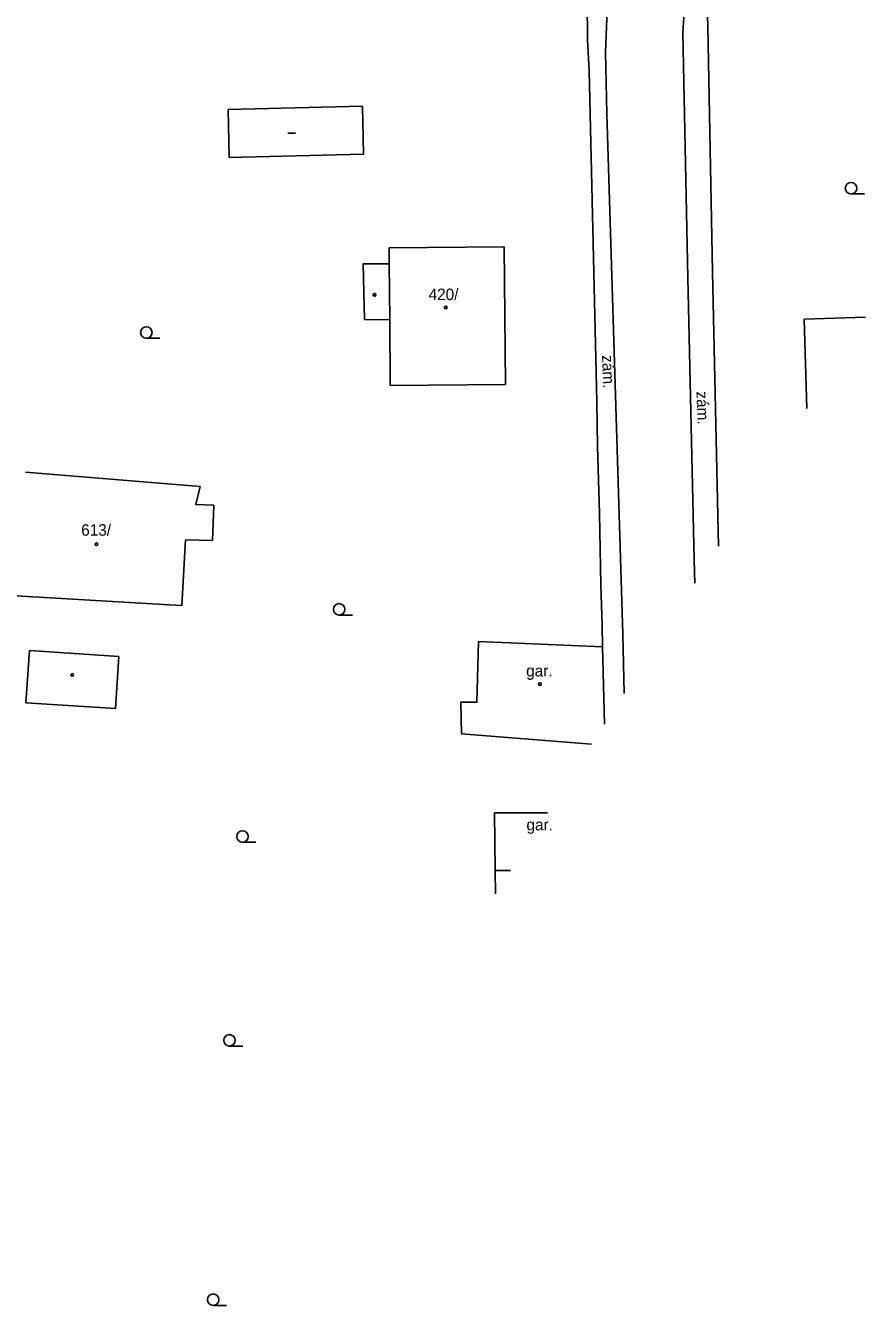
# Model space of a CAD drawing. Extents: x -737488 to -734267, y -1145775 to -1142573.
# Drawn here: x -736639.5 to -736584.6, y -1144538.2 to -1144454.6 of the extents above; entities that cross this region are included whole.
import ezdxf

# ---------------------------------------------------------------- set-up
doc = ezdxf.new("R2010")
doc.units = 0
for name, color, linetype in [('Vrstva 1', 7, 'Continuous'), ('Vrstva 10', 7, 'Continuous'), ('Vrstva 14', 7, 'Continuous'), ('Vrstva 3', 7, 'Continuous'), ('Vrstva 4', 7, 'Continuous'), ('Vrstva 5', 7, 'Continuous'), ('Vrstva 6', 7, 'Continuous'), ('Vrstva 8', 7, 'Continuous'), ('Vrstva 9', 7, 'Continuous')]:
    doc.layers.add(name, color=color, linetype=linetype)

# ---------------------------------------------------------------- blocks, each defined once
blk = doc.blocks.new('3.040')
at = {"layer": 'Vrstva 1'}
blk.add_line((0, -0.75), (1.75, -0.75), dxfattribs=at)
blk.add_circle((0, 0), 0.75, dxfattribs=at)
blk = doc.blocks.new('4.020')
at = {"layer": 'Vrstva 1'}
blk.add_circle((0, 0), 0.175, dxfattribs=at)
blk = doc.blocks.new('4.030')
at = {"layer": 'Vrstva 1'}
blk.add_line((-0.5, 0), (0.5, 0), dxfattribs=at)

msp = doc.modelspace()

# ---------------------------------------------------------------- linework, layer by layer
at = {"layer": 'Vrstva 10'}
for points in [[(-736601.42, -1144451.3), (-736601.61, -1144456.28)], [(-736596.56, -1144455.02), (-736596.37, -1144451.98)], [(-736596.23, -1144471.04), (-736596.56, -1144455.02)], [(-736601.61, -1144456.28), (-736601.53, -1144460.3)], [(-736601.53, -1144460.3), (-736601.08, -1144474.46)], [(-736595.82, -1144489.47), (-736596.23, -1144471.04)], [(-736601.08, -1144474.46), (-736600.49, -1144494.33)], [(-736595.766, -1144490.987), (-736595.82, -1144489.47)], [(-736600.49, -1144494.33), (-736600.393, -1144498.199)]]:
    msp.add_lwpolyline(points, dxfattribs=at)
at = {"layer": 'Vrstva 4'}
msp.add_lwpolyline([(-736601.8, -1144495.15), (-736601.682, -1144500.209)], dxfattribs=at)
at = {"layer": 'Vrstva 5'}
for points in [[(-736626.29, -1144460.03), (-736617.51, -1144459.82)], [(-736626.21, -1144463.17), (-736626.29, -1144460.03)], [(-736617.51, -1144459.82), (-736617.43, -1144462.96)], [(-736617.43, -1144462.96), (-736626.21, -1144463.17)], [(-736608.23, -1144469.02), (-736615.76, -1144469.08)], [(-736615.76, -1144469.08), (-736615.75, -1144470.13)], [(-736608.16, -1144478.01), (-736608.23, -1144469.02)], [(-736617.45, -1144470.13), (-736617.36, -1144473.76)], [(-736615.75, -1144470.13), (-736617.45, -1144470.13)], [(-736615.72, -1144473.77), (-736615.75, -1144470.13)], [(-736617.36, -1144473.76), (-736615.72, -1144473.77)], [(-736615.72, -1144473.77), (-736615.69, -1144478.07)], [(-736588.63, -1144473.73), (-736584.621, -1144473.614)], [(-736588.451, -1144479.583), (-736588.63, -1144473.73)], [(-736615.69, -1144478.07), (-736608.16, -1144478.01)], [(-736639.54, -1144483.73), (-736628.12, -1144484.68), (-736628.39, -1144485.85), (-736627.22, -1144485.9), (-736627.31, -1144488.2), (-736629.07, -1144488.16), (-736629.3, -1144492.45), (-736630.51, -1144492.38), (-736640.14, -1144491.82)], [(-736601.8, -1144495.15), (-736609.91, -1144494.8), (-736610.02, -1144498.77), (-736611.08, -1144498.77), (-736611.02, -1144500.84), (-736602.523, -1144501.52)], [(-736639.28, -1144495.4), (-736639.51, -1144498.81)], [(-736633.43, -1144495.79), (-736639.28, -1144495.4)], [(-736633.65, -1144499.19), (-736633.43, -1144495.79)], [(-736639.51, -1144498.81), (-736633.65, -1144499.19)], [(-736605.404, -1144506.01), (-736608.88, -1144506.01), (-736608.82, -1144509.77), (-736608.796, -1144511.299)], [(-736608.82, -1144509.77), (-736607.817, -1144509.773)]]:
    msp.add_lwpolyline(points, dxfattribs=at)
at = {"layer": 'Vrstva 9'}
for points in [[(-736602.79, -1144455.5), (-736602.81, -1144452.86)], [(-736594.92, -1144454.58), (-736594.96, -1144453.32)], [(-736594.89, -1144456.94), (-736594.92, -1144454.58)], [(-736602.79, -1144455.5), (-736602.67, -1144457.5)], [(-736602.18, -1144479.13), (-736602.67, -1144457.5)], [(-736594.89, -1144456.94), (-736594.61, -1144470.64)], [(-736594.61, -1144470.64), (-736594.223, -1144488.582)], [(-736602.18, -1144479.13), (-736602.13, -1144482.05)], [(-736602.01, -1144486.44), (-736602.13, -1144482.05)], [(-736601.91, -1144491.09), (-736602.01, -1144486.44)], [(-736601.91, -1144491.09), (-736601.83, -1144493.75)], [(-736601.83, -1144493.75), (-736601.8, -1144495.15)]]:
    msp.add_lwpolyline(points, dxfattribs=at)

# ---------------------------------------------------------------- block references
at = {"layer": 'Vrstva 3', "xscale": 0.5, "yscale": 0.5}
for p in [(-736585.56, -1144465.18), (-736631.63, -1144474.61), (-736619.03, -1144492.7), (-736625.34, -1144507.55), (-736626.2, -1144520.87), (-736627.26, -1144537.82)]:
    msp.add_blockref('3.040', p, dxfattribs=at)
at = {"layer": 'Vrstva 8', "xscale": 0.5, "yscale": 0.5}
for name, p in [('4.030', (-736622.12, -1144461.57)), ('4.020', (-736616.71, -1144472.14)), ('4.020', (-736612.06, -1144472.97)), ('4.020', (-736634.89, -1144488.45)), ('4.020', (-736636.47, -1144496.99)), ('4.020', (-736605.9, -1144497.59))]:
    msp.add_blockref(name, p, dxfattribs=at)

# ---------------------------------------------------------------- texts
at = {"layer": 'Vrstva 14'}
for p in [(-736601.84, -1144476.1), (-736595.67, -1144478.47)]:
    msp.add_text('zám.', height=0.75, rotation=272.196, dxfattribs=at).set_placement(p)
for p in [(-736606.8, -1144497.09), (-736606.78, -1144507.15)]:
    msp.add_text('gar.', height=0.75, dxfattribs=at).set_placement(p)
at = {"layer": 'Vrstva 6'}
for s, p in [('420/', (-736613.18, -1144472.49)), ('613/', (-736635.89, -1144487.89))]:
    msp.add_text(s, height=0.75, dxfattribs=at).set_placement(p)

doc.saveas('drawing.dxf')
